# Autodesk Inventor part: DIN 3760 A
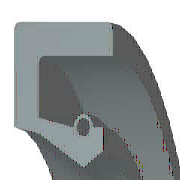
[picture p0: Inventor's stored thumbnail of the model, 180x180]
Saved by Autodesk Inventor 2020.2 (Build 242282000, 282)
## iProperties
Manager: www.cadconsulting.pl
Company: Fabian Stasiak CAD Consulting
Created: 2006-03
Part Number: DIN 3760 A
Material: TS
Description: Pierścień uszczelniający 22x35x7-NBR
Vendor: Autodesk Inc.
Document SubType Name: Modeling
Standard: DIN 3760
Designer: F.Stasiak
Standards Organization: DIN
Language: pl-PL
Size Designation: A - 22 x 35 x 7 - NBR
Categories: <MemberInstance Version="R10.0.0"><Categories><Category DisplayName="Części wałów" InternalName="7f7aeb1f-a693-4053-b835-cee3144e0d98" Mnemonic="SHFT"><Category
Stock Number: PFP 1Z22357
Project: Przekładnia X51
Density: 1.06 g/cm^3
Appearance: Tworzywo sztuczne (czarne)
Author: F.Stasiak
Subject: Zbiór ćwiczeń. Autodesk Inventor 2020. Kurs podstawowy
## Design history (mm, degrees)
revolve "Bryła" stored, may be unused: angle "d17" = 90 deg
revolve "Sprężyna1" stored, may be unused: angle "d18" = 90 deg
node "Bryła1"
node "Korpusy bryłowe"
node "Korpusy powierzchniowe"
sketch "Szkic1"
  geometry: L1 (0, 17.5)-(7, 17.5); L2 (7, 17.5)-(7, 16.25); L3 (7, 16.25)-(1.75, 16.25); L4 (0, 17.5)-(0, 13.1); L5 (0, 13.1)-(1.75, 12.75); L6 (1.75, 12.75)-(4.9, 11); L7 (4.9, 11)-(0, 11); L8 (6.3, 11.875)-(6.3, 13.1); L9 (0, 0)-(9.586, 0) reference; L10 (4.9, 11)-(6.3, 11.875); L11 (0, 19.5)-(0, -1.5) reference; L12 (-0.959, 0)-(12.461, 0) reference; L13 (4.2, 13.1)-(1.75, 13.59); L14 (1.75, 13.59)-(1.75, 16.25); L15 (6.3, 13.1)-(5.6, 13.1); C1 r 0.455 at (4.9, 13.1); A1 r 0.7 centre (4.9, 13.1) between (5.6, 13.1) and (4.2, 13.1)
  constraints: 26 end point, 5 horizontal alignment, 4 perpendicular, 2 centre point, 2 collinear, 2 horizontal, 2 parallel, 2 point on circle, 2 point on line, 2 vertical alignment, 1 coincident
  dimensions: "d0" = 35 diameter of L1 L9 (= SD2); "d1" = 23.75 diameter of L8.start L9 (= ABDM); "d2" = 1.25 distance of L1.end L2.end (computed from SD); "d3" = 0.91 diameter of C1 (= SPDI); "d4" = 1.4 diameter of A1 (= SPDA); "d5" = 22 diameter of L6.end L9 (= NND); "d6" = 25.5 diameter of L5.end L9 (= TKDM); "d7" = 26.2 diameter of L4.end L9 (= HLDM); "d8" = 4.9 distance from line of C1.centre L4 (= SPDST); "d9" = 6.3 distance between parallel lines of L8 L4 (= SDI); "d10" = 7 distance between parallel lines of L2 L4 (= SWDT); "d12" = 1.75 distance between parallel lines of L14 L4 (= SD)
fillet "Zaokrąglenie1" dims "d11" = 0.3 (= RR)
other parameters: "SD2" = 35 [user parameter; used in 1 equation term], "SWDT" = 7 [user parameter; used in 1 equation term], "RR" = 0.3 [user parameter; used in 1 equation term], "SD" = 1.75 [user parameter; used in 2 equation terms], "NND" = 22 [user parameter; used in 1 equation term], "SPDA" = 1.4 [user parameter; used in 1 equation term], "SPDI" = 0.91 [user parameter; used in 1 equation term], "TKDM" = 25.5 [user parameter; used in 1 equation term], "HLDM" = 26.2 [user parameter; used in 1 equation term], "ABDM" = 23.75 [user parameter; used in 1 equation term], "SDI" = 6.3 [user parameter; used in 1 equation term], "SPDST" = 4.9 [user parameter; used in 1 equation term], "d13" = 0, "d14" = 0, "d15" = 0, "LAB" = 0.35 [user parameter]
